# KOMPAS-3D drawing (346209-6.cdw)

Referenced files: С1-2.cdw
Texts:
  КП.ОКМЧЕП.МЕ.12-01.000СП
  Текст на чертеже
  Размерные надписи
  Шероховатость
  Линия-выноска #1
  Линия-выноска #2
  Линия-выноска #3
  Отклонения формы и база
  Заголовок таблицы
  Ячейка таблицы
  Стрелка вида
  Обозначение изменения
  Фигурная скобка
  Номер узла
  Марка координационной оси
  VRCB
  Выносная надпись
  Обозначение узла
  Марка/позиционное обозначение с линией-выноской
  Марка/позиционное обозначение на линии
  Марка/позиционное обозначение без линии-выноски
  Шпонки ГОСТ 23360-78
  КП.ОКМЧЕП.МЕ.34.01.000СП-
  ГОСТ 3129-70
  Штіфт
  Масло И-100A
  ТУ 38-101413-78
  Мастило ЯНЗ -2
  ГОСТ 9432-60
Dimensions and other numbers on the sheet: 7; 1:1; 1; 35; 36; 37; 2 х 8 х 63; 38; 4 х 9 х 36; 41; 2; 0; 3; 4; 5; 6; 8; 9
